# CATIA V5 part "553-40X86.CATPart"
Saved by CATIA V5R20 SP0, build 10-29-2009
Part number: 553-40X86
Definition: NONE
Nomenclature: 553-40X86
Source: Unknown
Description: 553-40X86
Bounding box of the stored display mesh (mm): x 0 to 86, y -29.5 to 29.5, z -29.5 to 29.5
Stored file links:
  C:\Users\Utente\Desktop\IO LAVORO\3D X SITO CF\X SITO\PLASTICA\553\553-40X86.CATPart
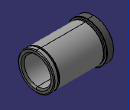
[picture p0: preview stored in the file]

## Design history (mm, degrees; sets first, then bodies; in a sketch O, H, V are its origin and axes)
Body1 "553-40X86" (main body)
  Solid1: solid without history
